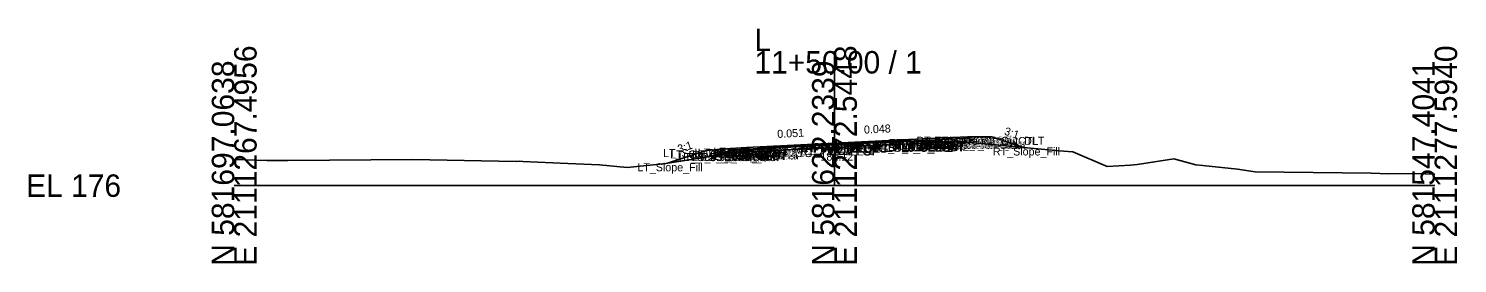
# Model space of a CAD drawing. Extents: x -486 to 1153, y -333 to 9539.
# Drawn here: x -25.7 to 152.8, y 990.3 to 1019.6 of the extents above; entities that cross this region are included whole.
import ezdxf

# ---------------------------------------------------------------- set-up
doc = ezdxf.new("R2010")
doc.units = 0
for name, color, linetype in [('Default', 7, 'Continuous'), ('Exist CMT Pavement', 7, 'Continuous'), ('Exist Cross Section Cell', 7, 'Continuous'), ('Exist XS Ground Line', 7, 'Continuous'), ('Prop CMT Pvmt Course 1', 7, 'Continuous'), ('Prop CMT Pvmt Course 1 Wedge', 7, 'Continuous'), ('Prop CMT Pvmt Course 2', 7, 'Continuous'), ('Prop CMT Pvmt Course 2 Wedge', 7, 'Continuous'), ('Prop CMT Pvmt Course 3', 7, 'Continuous'), ('Prop CMT Pvmt Course 3 Wedge', 7, 'Continuous'), ('Prop CMT Pvmt Surface', 7, 'Continuous'), ('Prop CMT Pvmt Surface Shoulder', 7, 'Continuous'), ('Prop CMT Pvmt Wedge Surface 1', 7, 'Continuous'), ('Prop CMT Pvmt Wedge Surface 2', 7, 'Continuous'), ('Prop CMT Pvmt Wedge Surface 3', 7, 'Continuous'), ('Prop CMT Shld Paved Course 1', 7, 'Continuous'), ('Prop CMT Shld Paved Course 2', 7, 'Continuous'), ('Prop CMT Shld Paved Course 3', 7, 'Continuous'), ('Prop CMT Slope Grass', 7, 'Continuous'), ('Prop CMT Subgrade Earthwork', 7, 'Continuous'), ('Prop XS Earthwork Shape', 7, 'Continuous'), ('Prop XS SE Text', 7, 'Continuous'), ('Prop XS Side Slope Text', 7, 'Continuous'), ('Scratch_Level_0', 7, 'Continuous'), ('Scratch_Level_1', 7, 'Continuous')]:
    doc.layers.add(name, color=color, linetype=linetype)

msp = doc.modelspace()

# ---------------------------------------------------------------- linework, layer by layer
at = {"layer": 'Exist CMT Pavement'}
for points in [[(75, 1005.12), (84.59, 1005.5)], [(65.39, 1004.56), (75, 1005.12)]]:
    msp.add_lwpolyline(points, dxfattribs=at)
at = {"layer": 'Exist Cross Section Cell'}
for p, q in [((75, 1000), (75, 1016.78)), ((0, 1000), (75, 1000)), ((75, 1000), (150, 1000))]:
    msp.add_line(p, q, dxfattribs=at)
at = {"layer": 'Exist XS Ground Line'}
for p, q in [((75.08, 1005.12), (84.58, 1005.5)), ((84.58, 1005.5), (86.42, 1005.59)), ((86.42, 1005.59), (92.44, 1005.34)), ((92.44, 1005.34), (103.08, 1004.35)), ((53.94, 1002.76), (61.08, 1003.9)), ((61.08, 1003.9), (65.38, 1004.56)), ((65.38, 1004.56), (73.76, 1005.06)), ((73.76, 1005.06), (74.39, 1005.1)), ((74.39, 1005.1), (75.08, 1005.12)), ((103.08, 1004.35), (104.77, 1004.21)), ((104.77, 1004.21), (109.06, 1002.37)), ((113.13, 1002.67), (117.41, 1003.35)), ((117.41, 1003.35), (120.15, 1002.6)), ((0, 1003.24), (4.07, 1003.14)), ((4.07, 1003.14), (6.72, 1003.13)), ((6.72, 1003.13), (22.26, 1003.27)), ((22.26, 1003.27), (35.23, 1003.01)), ((35.23, 1003.01), (35.61, 1003.06)), ((35.61, 1003.06), (36.05, 1003)), ((36.05, 1003), (41.67, 1002.75)), ((41.67, 1002.75), (45.63, 1002.58)), ((45.63, 1002.58), (49.12, 1002.27)), ((49.12, 1002.27), (53.2, 1002.66)), ((53.2, 1002.66), (53.94, 1002.76)), ((109.06, 1002.37), (112.01, 1002.56)), ((112.01, 1002.56), (112.81, 1002.62)), ((112.81, 1002.62), (113.13, 1002.67)), ((120.15, 1002.6), (121.02, 1002.5)), ((121.02, 1002.5), (125.36, 1002.05)), ((125.36, 1002.05), (127.56, 1001.73)), ((127.56, 1001.73), (142.07, 1001.55)), ((142.07, 1001.55), (144.29, 1001.49)), ((144.29, 1001.49), (147.53, 1001.5)), ((147.53, 1001.5), (150, 1001.43))]:
    msp.add_line(p, q, dxfattribs=at)
at = {"layer": 'Prop CMT Pvmt Course 1'}
for points in [[(75, 1005.3), (64, 1004.74)], [(65.39, 1004.68), (75, 1005.18)], [(75, 1005.3), (86, 1005.83)], [(84.59, 1005.64), (75, 1005.18)], [(75, 1005.09), (75, 1005.3)], [(75, 1005.09), (75, 1005.3)], [(75, 1005.18), (75, 1005.09), (75, 1005.09)], [(75, 1005.18), (75, 1005.09), (75, 1005.09)], [(84.59, 1005.56), (84.59, 1005.64)], [(86, 1005.62), (84.59, 1005.56)], [(86, 1005.83), (86, 1005.62)], [(64, 1004.74), (64, 1004.53)], [(64, 1004.53), (65.39, 1004.6)], [(65.39, 1004.6), (65.39, 1004.68)]]:
    msp.add_lwpolyline(points, dxfattribs=at)
at = {"layer": 'Prop CMT Pvmt Course 1 Wedge'}
for points in [[(75, 1005.18), (65.39, 1004.68)], [(75, 1005.18), (84.59, 1005.64)]]:
    msp.add_lwpolyline(points, dxfattribs=at)
at = {"layer": 'Prop CMT Pvmt Course 2'}
for points in [[(84.59, 1005.56), (86, 1005.62)], [(84.59, 1005.22), (84.59, 1005.56)], [(86, 1005.29), (84.59, 1005.22)], [(86, 1005.62), (86, 1005.29)], [(65.39, 1004.6), (64, 1004.53)], [(64, 1004.53), (64, 1004.2)], [(64, 1004.2), (65.39, 1004.27)], [(65.39, 1004.27), (65.39, 1004.6)]]:
    msp.add_lwpolyline(points, dxfattribs=at)
at = {"layer": 'Prop CMT Pvmt Course 2 Wedge'}
for points in [[(75, 1005.09), (84.59, 1005.56)], [(75, 1005.09), (65.39, 1004.6)]]:
    msp.add_lwpolyline(points, dxfattribs=at)
at = {"layer": 'Prop CMT Pvmt Course 3'}
for points in [[(84.59, 1005.22), (86, 1005.29)], [(84.59, 1005.22), (84.59, 1005.22)], [(86, 1005.29), (86, 1005.29)], [(65.39, 1004.27), (64, 1004.2)], [(64, 1004.2), (64, 1004.2)], [(65.39, 1004.27), (65.39, 1004.27)]]:
    msp.add_lwpolyline(points, dxfattribs=at)
at = {"layer": 'Prop CMT Pvmt Course 3 Wedge'}
for points in [[(75, 1004.76), (84.59, 1005.22)], [(75, 1004.76), (65.39, 1004.27)]]:
    msp.add_lwpolyline(points, dxfattribs=at)
at = {"layer": 'Prop CMT Pvmt Surface'}
for points in [[(75, 1005.3), (64, 1004.74)], [(75, 1005.3), (86, 1005.83)]]:
    msp.add_lwpolyline(points, dxfattribs=at)
at = {"layer": 'Prop CMT Pvmt Surface Shoulder'}
for points in [[(86, 1005.83), (91.62, 1006.1)], [(64, 1004.74), (62, 1004.63)]]:
    msp.add_lwpolyline(points, dxfattribs=at)
at = {"layer": 'Prop CMT Pvmt Wedge Surface 1'}
for points in [[(75, 1005.18), (65.39, 1004.68)], [(75, 1005.18), (84.59, 1005.64)], [(84.59, 1005.64), (84.59, 1005.56)], [(84.59, 1005.56), (86, 1005.62)], [(86, 1005.62), (86, 1005.83)], [(64, 1004.53), (64, 1004.74)], [(65.39, 1004.6), (64, 1004.53)], [(65.39, 1004.68), (65.39, 1004.6)]]:
    msp.add_lwpolyline(points, dxfattribs=at)
at = {"layer": 'Prop CMT Pvmt Wedge Surface 2'}
for points in [[(75, 1005.09), (86, 1005.62)], [(86, 1005.62), (86, 1005.83)], [(75, 1005.09), (64, 1004.53)], [(64, 1004.53), (64, 1004.74)]]:
    msp.add_lwpolyline(points, dxfattribs=at)
at = {"layer": 'Prop CMT Pvmt Wedge Surface 3'}
for points in [[(75, 1004.76), (86, 1005.29)], [(86, 1005.29), (86, 1005.83)], [(75, 1004.76), (64, 1004.2)], [(64, 1004.2), (64, 1004.74)]]:
    msp.add_lwpolyline(points, dxfattribs=at)
at = {"layer": 'Prop CMT Shld Paved Course 1'}
for points in [[(86, 1005.83), (91.62, 1006.1), (91.82, 1005.91)], [(91.82, 1005.91), (86, 1005.62)], [(86, 1005.62), (86, 1005.83)], [(64, 1004.74), (62, 1004.63), (61.78, 1004.41)], [(61.78, 1004.41), (64, 1004.53)], [(64, 1004.53), (64, 1004.74)]]:
    msp.add_lwpolyline(points, dxfattribs=at)
at = {"layer": 'Prop CMT Shld Paved Course 2'}
for points in [[(86, 1005.62), (91.82, 1005.91), (92.14, 1005.59)], [(86, 1005.29), (86, 1005.62)], [(92.14, 1005.59), (86, 1005.29)], [(64, 1004.53), (61.78, 1004.41), (61.43, 1004.06)], [(61.43, 1004.06), (64, 1004.2)], [(64, 1004.2), (64, 1004.53)]]:
    msp.add_lwpolyline(points, dxfattribs=at)
at = {"layer": 'Prop CMT Shld Paved Course 3'}
for points in [[(86, 1005.29), (92.14, 1005.59)], [(86, 1005.29), (86, 1005.29)], [(92.14, 1005.59), (92.14, 1005.59), (92.14, 1005.59)], [(64, 1004.2), (61.43, 1004.06)], [(61.43, 1004.06), (61.43, 1004.06), (61.43, 1004.06)], [(64, 1004.2), (64, 1004.2)]]:
    msp.add_lwpolyline(points, dxfattribs=at)
at = {"layer": 'Prop CMT Slope Grass'}
for points in [[(91.62, 1006.1), (94.67, 1006.07), (98.62, 1004.76)], [(62, 1004.63), (59, 1004.39), (54.14, 1002.79)]]:
    msp.add_lwpolyline(points, dxfattribs=at)
at = {"layer": 'Prop CMT Subgrade Earthwork'}
for points in [[(84.59, 1005.22), (84.59, 1005.5)], [(84.59, 1005.22), (86, 1005.29)], [(86, 1005.29), (92.14, 1005.59)], [(92.14, 1005.59), (92.65, 1006.09)], [(61.43, 1004.06), (60.94, 1004.55)], [(64, 1004.2), (61.43, 1004.06)], [(65.39, 1004.27), (64, 1004.2)], [(65.39, 1004.27), (65.39, 1004.56)]]:
    msp.add_lwpolyline(points, dxfattribs=at)
at = {"layer": 'Prop XS Earthwork Shape'}
for points in [[(86, 1005.29), (89.53, 1005.46), (86.42, 1005.59), (84.59, 1005.5), (84.59, 1005.22)], [(92.44, 1005.34), (98.62, 1004.76), (94.67, 1006.07), (92.65, 1006.09), (92.14, 1005.59), (89.53, 1005.46)], [(61.08, 1003.9), (62.53, 1004.12), (61.43, 1004.06), (60.94, 1004.55), (59, 1004.39), (54.14, 1002.79)], [(65.39, 1004.27), (64, 1004.2), (62.53, 1004.12), (65.39, 1004.56)], [(65.39, 1004.56), (73.76, 1005.06), (74.39, 1005.1), (75, 1005.12)]]:
    msp.add_lwpolyline(points, close=True, dxfattribs=at)
at = {"layer": 'Scratch_Level_1'}
msp.add_line((84.59, 1005.5), (74.98, 1005.12), dxfattribs=at)
for points in [[(65.39, 1004.68), (75, 1005.17)], [(75, 1005.17), (84.59, 1005.64)], [(84.59, 1005.64), (84.59, 1005.5)], [(74.98, 1005.12), (65.39, 1004.56)], [(65.39, 1004.6), (65.39, 1004.68)], [(65.39, 1004.56), (65.39, 1004.6)]]:
    msp.add_lwpolyline(points, dxfattribs=at)

# ---------------------------------------------------------------- texts
at = {"layer": 'Default'}
for s, height, p in [('181.12', 1, (73.25, 1003.12)), ('-', 0.0001, (0, 1000))]:
    msp.add_text(s, height=height, dxfattribs=at).set_placement(p)
at = {"layer": 'Exist Cross Section Cell'}
for s, p in [('L', (65, 1016.78)), ('11+50.00 / 1', (65, 1013.98)), ('EL 176', (-26, 998.6))]:
    msp.add_text(s, height=2.8, dxfattribs=at).set_placement(p)
for s, p in [('E 2111267.4956', (2.8, 990)), ('E 2111272.5448', (77.8, 990)), ('E 2111277.5940', (152.8, 990)), ('N 581697.0638', (0, 990)), ('N 581622.2339', (75, 990)), ('N 581547.4041', (150, 990))]:
    msp.add_text(s, height=2.8, rotation=90, dxfattribs=at).set_placement(p)
at = {"layer": 'Prop XS SE Text'}
for s, rotation, p in [('0.051', 2.931, (67.88, 1005.94)), ('0.048', 2.7698, (78.71, 1006.48))]:
    msp.add_text(s, height=1, rotation=rotation, dxfattribs=at).set_placement(p)
at = {"layer": 'Prop XS Side Slope Text'}
for rotation, p in [(341.7371, (96.13, 1006.38)), (18.2629, (55.58, 1004.06))]:
    msp.add_text('3:1', height=1, rotation=rotation, dxfattribs=at).set_placement(p)
at = {"layer": 'Scratch_Level_0'}
for s, p in [('RT_PV1_IEEOP', (70.83, 1004.18)), ('LT_PV1_IEEOP', (70.89, 1004.18)), ('PV1_PGL', (72.47, 1004.3)), ('RT_PV_OEEOP_EG', (79.13, 1004.5)), ('RT_Sub Tie Out', (79.68, 1004.5)), ('RT_PV2_OEEOP', (79.92, 1004.56)), ('RT_PV3_OEEOP', (79.92, 1004.22)), ('RT_Sub_OEEOP', (79.95, 1004.22)), ('RT_PV1_OEEOP', (80.04, 1004.64)), ('RT_PV2_OEOT', (81.69, 1004.62)), ('RT_PV3_OEOT', (81.69, 1004.29)), ('RT_Sub_OEOT', (81.71, 1004.29)), ('RT_PV1_OEOT', (81.81, 1004.83)), ('RT_Sub_Trench_Out_DLT', (85.24, 1005.09)), ('RT_Sub_Trench_Out', (86.19, 1004.59)), ('RT_PS3_Shelf_Out', (86.74, 1004.59)), ('RT_PS1_OEOP', (87.47, 1005.1)), ('RT_PS2_OEOP', (87.55, 1004.91)), ('RT_PS3_OEOP', (87.87, 1004.59)), ('RT_GS_OS_CTL', (90.07, 1005.07)), ('LT_Sub_Trench_Out_DLT', (53.59, 1003.55)), ('LT_GS_OS_CTL', (54.46, 1003.39)), ('LT_Sub_Trench_Out', (55.54, 1003.06)), ('LT_PS3_Shelf_Out', (56.09, 1003.06)), ('LT_PS3_OEOP', (57.22, 1003.06)), ('LT_PS2_OEOP', (57.57, 1003.41)), ('LT_PS1_OEOP', (57.91, 1003.63)), ('LT_PV2_OEOT', (59.75, 1003.53)), ('LT_PV3_OEOT', (59.75, 1003.2)), ('LT_Sub_OEOT', (59.77, 1003.2)), ('LT_PV1_OEOT', (59.87, 1003.74)), ('LT_PV_OEEOP_EG', (59.99, 1003.56)), ('LT_Sub Tie Out', (60.55, 1003.56)), ('LT_PV2_OEEOP', (60.78, 1003.6)), ('LT_PV3_OEEOP', (60.78, 1003.27)), ('LT_Sub_OEEOP', (60.81, 1003.27)), ('LT_PV1_OEEOP', (60.9, 1003.68)), ('RT_PV_IEEOP_EG', (69.92, 1004.12)), ('LT_PV_IEEOP_EG', (69.98, 1004.12)), ('RT_PV2_IEEOP', (70.71, 1004.09)), ('RT_PV3_IEEOP', (70.71, 1003.76)), ('LT_PV2_IEEOP', (70.77, 1004.09)), ('LT_PV3_IEEOP', (70.77, 1003.76)), ('PV2_PGL', (72.35, 1004.09)), ('RT_Slope_Fill', (94.8, 1003.76)), ('LT_Slope_Fill', (50.37, 1001.79))]:
    msp.add_text(s, height=1, dxfattribs=at).set_placement(p)

doc.saveas('drawing.dxf')
